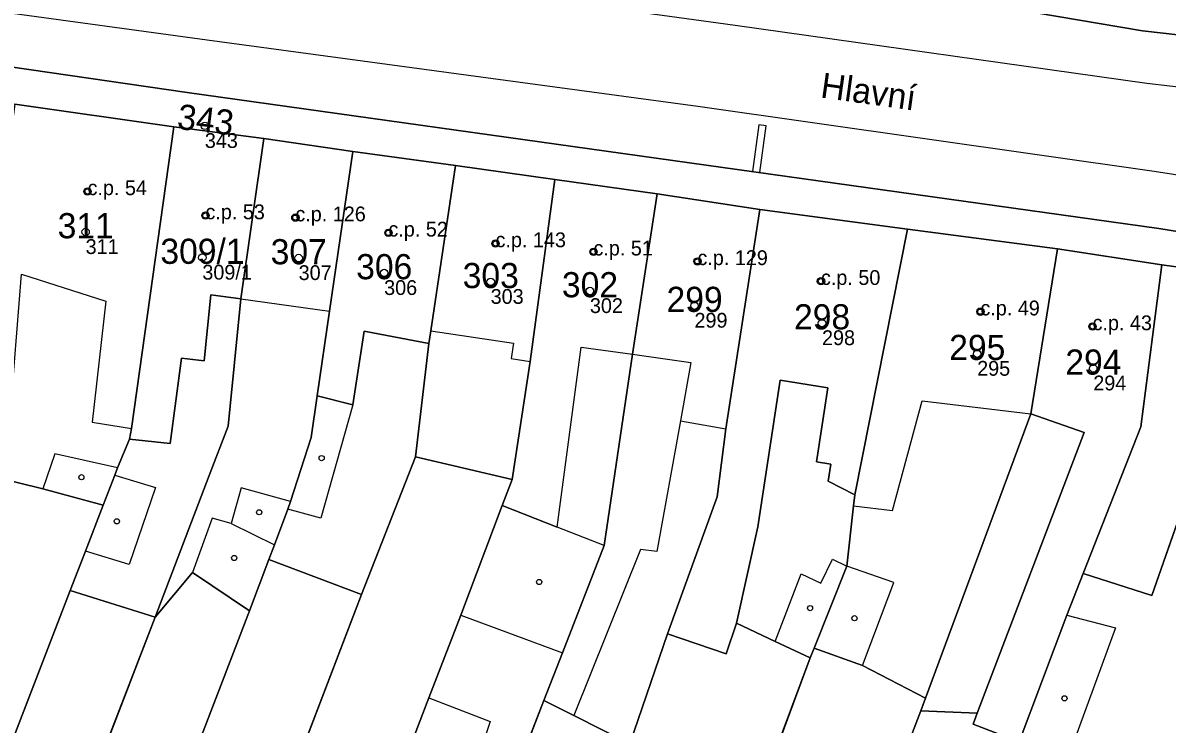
# Model space of a CAD drawing. Extents: x -603967 to -594699, y -1179315 to -1165625.
# Drawn here: x -597781.7 to -597704.3, y -1172370 to -1172322.6 of the extents above; entities that cross this region are included whole.
import ezdxf

# ---------------------------------------------------------------- set-up
doc = ezdxf.new("R2010")
doc.units = 0
for name, color, linetype in [('Definiční body', 7, 'Continuous'), ('Hranice parcel', 7, 'Continuous'), ('Parcelní čísla', 7, 'Continuous'), ('Polygon budovy', 7, 'Continuous'), ('Polygon parcely', 7, 'Continuous'), ('Pop  PČ popisy', 7, 'Continuous'), ('Vnitřní kresba', 7, 'Continuous'), ('Věcná břemena k části', 7, 'Continuous'), ('Značky budov', 7, 'Continuous')]:
    doc.layers.add(name, color=color, linetype=linetype)

msp = doc.modelspace()

# ---------------------------------------------------------------- linework, layer by layer
at = {"layer": 'Definiční body'}
for centre in [(-597769.38, -1172329.59994), (-597777.31, -1172334.02994), (-597769.34, -1172335.65994), (-597763.26, -1172335.79994), (-597777.44, -1172336.76994), (-597756.97, -1172336.82994), (-597749.73, -1172337.54994), (-597743.11, -1172338.10994), (-597769.55, -1172338.49994), (-597763.04, -1172338.52994), (-597736.08, -1172338.75994), (-597757.26, -1172339.53994), (-597750.06, -1172340.13994), (-597727.73, -1172340.09994), (-597743.35, -1172340.75994), (-597736.28, -1172341.74994), (-597716.95, -1172342.15994), (-597727.66, -1172342.92994), (-597709.37, -1172343.15994), (-597717.17, -1172344.99994), (-597709.32, -1172345.98994)]:
    msp.add_circle(centre, 0.25, dxfattribs=at)
at = {"layer": 'Hranice parcel'}
for p, q in [((-597771.48, -1172329.67), (-597782.22, -1172328.12)), ((-597765.4, -1172330.46), (-597771.48, -1172329.67)), ((-597765.4, -1172330.46), (-597766.94, -1172341.3)), ((-597759.38, -1172331.34), (-597765.4, -1172330.46)), ((-597760.96, -1172342.12), (-597759.38, -1172331.34)), ((-597759.38, -1172331.34), (-597752.44, -1172332.27)), ((-597745.71, -1172333.23), (-597752.44, -1172332.27)), ((-597738.8, -1172334.2), (-597745.71, -1172333.23)), ((-597731.86, -1172335.26), (-597738.8, -1172334.2)), ((-597721.89, -1172336.59), (-597731.86, -1172335.26)), ((-597721.89, -1172336.59), (-597725.43, -1172354.54)), ((-597711.75, -1172337.91), (-597721.89, -1172336.59)), ((-597704.68, -1172338.99), (-597711.75, -1172337.91)), ((-597691.02, -1172340.89), (-597704.68, -1172338.99)), ((-597754.24, -1172344.3), (-597755.15, -1172351.97)), ((-597763.58, -1172355), (-597762.19, -1172350.67)), ((-597755.15, -1172351.97), (-597758.79, -1172361.28)), ((-597755.15, -1172351.97), (-597748.61, -1172353.5)), ((-597769.08, -1172353.23), (-597772.73, -1172362.82)), ((-597766.37, -1172362.38), (-597765.05, -1172358.92)), ((-597758.79, -1172361.28), (-597765.05, -1172358.92)), ((-597710, -1172359.85), (-597711.11, -1172362.67)), ((-597778.48, -1172361.01), (-597796.02, -1172406.49)), ((-597758.79, -1172361.28), (-597789.15, -1172440.56)), ((-597778.48, -1172361.01), (-597772.73, -1172362.82)), ((-597772.73, -1172362.82), (-597801.55, -1172437.37)), ((-597793.43, -1172432.8), (-597766.37, -1172362.38)), ((-597711.11, -1172362.67), (-597714.34, -1172371.24)), ((-597733.43, -1172363.22), (-597730.82, -1172364.45)), ((-597740.64, -1172371.37), (-597738.11, -1172363.93)), ((-597730.82, -1172364.45), (-597728.45, -1172365.57)), ((-597728.2, -1172364.9), (-597728.45, -1172365.57)), ((-597728.2, -1172364.9), (-597724.93, -1172366.07)), ((-597728.45, -1172365.57), (-597747.04, -1172415.37)), ((-597724.93, -1172366.07), (-597720.66, -1172368.28)), ((-597746.46, -1172368.45), (-597748.35, -1172373.32)), ((-597720.66, -1172368.28), (-597720.99, -1172369.15)), ((-597720.99, -1172369.15), (-597752, -1172449.92))]:
    msp.add_line(p, q, dxfattribs=at)
for points in [[(-597661.75, -1172328.26), (-597662.94, -1172328.05), (-597706, -1172323.18), (-597731.68, -1172318.8)], [(-597737.75, -1172331.93), (-597770.58, -1172327.35), (-597797.27, -1172323.47)], [(-597771.48, -1172329.67), (-597774.33, -1172350.05), (-597774.47, -1172350.77), (-597775.28, -1172352.71)], [(-597752.44, -1172332.27), (-597754.11, -1172343.45), (-597754.24, -1172344.3)], [(-597674.14, -1172341.49), (-597704.89, -1172336.54), (-597737.75, -1172331.93)], [(-597745.71, -1172333.23), (-597747.39, -1172345.52), (-597748.61, -1172353.5)], [(-597738.8, -1172334.2), (-597740.48, -1172345.04), (-597742.38, -1172357.97), (-597745.2, -1172365.21), (-597746.46, -1172368.45)], [(-597731.86, -1172335.26), (-597734.16, -1172350.08), (-597734.74, -1172354.68), (-597738.11, -1172363.93)], [(-597711.75, -1172337.91), (-597713.55, -1172349.07), (-597720.66, -1172368.28)], [(-597704.68, -1172338.99), (-597706.11, -1172349.95), (-597710, -1172359.85)], [(-597766.94, -1172341.3), (-597767.81, -1172349.9), (-597769.08, -1172353.23)], [(-597762.19, -1172350.67), (-597761.78, -1172347.85), (-597760.96, -1172342.12)], [(-597776.25, -1172355.24), (-597780.33, -1172354.14), (-597787.02, -1172352.5)], [(-597775.28, -1172352.71), (-597775.47, -1172353.21), (-597776.25, -1172355.24)], [(-597748.61, -1172353.5), (-597749.28, -1172355.27), (-597752.08, -1172362.67), (-597754.24, -1172368.26), (-597755.24, -1172370.86)], [(-597765.05, -1172358.92), (-597764.67, -1172357.92), (-597763.77, -1172355.5), (-597763.58, -1172355)], [(-597725.43, -1172354.54), (-597725.53, -1172355.28), (-597725.99, -1172359.36), (-597728.2, -1172364.9)], [(-597776.25, -1172355.24), (-597777.45, -1172358.34), (-597778.48, -1172361.01)], [(-597772.73, -1172362.82), (-597770.22, -1172359.79), (-597766.37, -1172362.38)], [(-597738.11, -1172363.93), (-597734.13, -1172365.28), (-597733.43, -1172363.22)], [(-597746.46, -1172368.45), (-597744.44, -1172369.46), (-597740.64, -1172371.37)], [(-597714.34, -1172371.24), (-597717.44, -1172370.05), (-597717.16, -1172369.3), (-597720.99, -1172369.15)]]:
    msp.add_lwpolyline(points, dxfattribs=at)
at = {"layer": 'Polygon budovy'}
for points in [[(-597771.48, -1172329.67), (-597782.22, -1172328.12), (-597784.8, -1172347.36), (-597782.4, -1172347.55), (-597781.78, -1172339.62), (-597776.08, -1172341.44), (-597776.99, -1172349.62), (-597774.33, -1172350.05)], [(-597774.47, -1172350.77), (-597771.73, -1172351.06), (-597770.97, -1172345.31), (-597769.43, -1172345.48), (-597768.97, -1172341.02), (-597766.94, -1172341.3), (-597765.4, -1172330.46), (-597771.48, -1172329.67), (-597774.33, -1172350.05)], [(-597765.4, -1172330.46), (-597766.94, -1172341.3), (-597760.96, -1172342.12), (-597759.38, -1172331.34)], [(-597761.78, -1172347.85), (-597759.37, -1172348.45), (-597758.62, -1172343.47), (-597754.24, -1172344.3), (-597754.11, -1172343.45), (-597752.44, -1172332.27), (-597759.38, -1172331.34), (-597760.96, -1172342.12)], [(-597752.44, -1172332.27), (-597754.11, -1172343.45), (-597748.52, -1172344.29), (-597748.68, -1172345.32), (-597747.39, -1172345.52), (-597745.71, -1172333.23)], [(-597748.61, -1172353.5), (-597749.28, -1172355.27), (-597745.56, -1172356.72), (-597743.93, -1172344.56), (-597740.48, -1172345.04), (-597738.8, -1172334.2), (-597745.71, -1172333.23), (-597747.39, -1172345.52)], [(-597737.23, -1172349.53), (-597734.16, -1172350.08), (-597731.86, -1172335.26), (-597738.8, -1172334.2), (-597740.48, -1172345.04), (-597736.52, -1172345.59)], [(-597738.11, -1172363.93), (-597734.13, -1172365.28), (-597733.43, -1172363.22), (-597731.99, -1172356.71), (-597730.48, -1172346.79), (-597727.26, -1172347.3), (-597728.04, -1172352.3), (-597727.06, -1172352.46), (-597727.24, -1172353.62), (-597725.43, -1172354.54), (-597721.89, -1172336.59), (-597731.86, -1172335.26), (-597734.16, -1172350.08), (-597734.74, -1172354.68)], [(-597725.43, -1172354.54), (-597725.53, -1172355.28), (-597722.9, -1172355.59), (-597720.88, -1172348.19), (-597713.55, -1172349.07), (-597711.75, -1172337.91), (-597721.89, -1172336.59)], [(-597717.44, -1172370.05), (-597714.34, -1172371.24), (-597711.11, -1172362.67), (-597710, -1172359.85), (-597706.11, -1172349.95), (-597704.68, -1172338.99), (-597711.75, -1172337.91), (-597713.55, -1172349.07), (-597709.94, -1172350.33), (-597717.16, -1172369.3)], [(-597706.11, -1172349.95), (-597710, -1172359.85), (-597705.37, -1172361.34), (-597701.54, -1172350.39), (-597699.58, -1172350.78), (-597692.76, -1172351.8), (-597691.02, -1172340.89), (-597704.68, -1172338.99)]]:
    msp.add_lwpolyline(points, close=True, dxfattribs=at)
at = {"layer": 'Polygon parcely'}
for points in [[(-597534.75, -1172348.6), (-597559.28, -1172345.76), (-597603.32, -1172338.5), (-597661.75, -1172328.26), (-597662.94, -1172328.05), (-597706, -1172323.18), (-597731.68, -1172318.8), (-597765.64, -1172314.46), (-597793.13, -1172310.44), (-597851.99, -1172302.61), (-597960.77, -1172287.58), (-597964.7, -1172286.91), (-597986.41, -1172283.87), (-598031.69, -1172277.53)], [(-598037.57, -1172289.67), (-597969.21, -1172299.41), (-597966.22, -1172299.84), (-597956.98, -1172301.12), (-597797.27, -1172323.47), (-597770.58, -1172327.35), (-597737.75, -1172331.93), (-597704.89, -1172336.54), (-597674.14, -1172341.49), (-597673.16, -1172341.62), (-597665.62, -1172342.61), (-597661.18, -1172343.19), (-597660.8, -1172342.11), (-597591.42, -1172351.56), (-597523.81, -1172359.42)], [(-597674.14, -1172341.49), (-597704.89, -1172336.54), (-597737.75, -1172331.93), (-597770.58, -1172327.35), (-597797.27, -1172323.47), (-597956.98, -1172301.12)], [(-597851.99, -1172302.61), (-597793.13, -1172310.44), (-597765.64, -1172314.46), (-597731.68, -1172318.8), (-597706, -1172323.18), (-597662.94, -1172328.05)], [(-597837.68, -1172320.18), (-597823.64, -1172322), (-597812.09, -1172323.71), (-597798.01, -1172325.85), (-597791.02, -1172326.88), (-597782.22, -1172328.12), (-597771.48, -1172329.67), (-597765.4, -1172330.46), (-597759.38, -1172331.34), (-597752.44, -1172332.27), (-597745.71, -1172333.23), (-597738.8, -1172334.2), (-597731.86, -1172335.26), (-597721.89, -1172336.59), (-597711.75, -1172337.91), (-597704.68, -1172338.99), (-597691.02, -1172340.89)]]:
    msp.add_lwpolyline(points, dxfattribs=at)
for points in [[(-597782.22, -1172328.12), (-597784.8, -1172347.36), (-597785.63, -1172349.15), (-597787.02, -1172352.5), (-597780.33, -1172354.14), (-597776.25, -1172355.24), (-597775.47, -1172353.21), (-597775.28, -1172352.71), (-597774.47, -1172350.77), (-597774.33, -1172350.05), (-597771.48, -1172329.67)], [(-597771.48, -1172329.67), (-597774.33, -1172350.05), (-597774.47, -1172350.77), (-597775.28, -1172352.71), (-597775.47, -1172353.21), (-597776.25, -1172355.24), (-597777.45, -1172358.34), (-597778.48, -1172361.01), (-597772.73, -1172362.82), (-597769.08, -1172353.23), (-597767.81, -1172349.9), (-597766.94, -1172341.3), (-597765.4, -1172330.46)], [(-597766.37, -1172362.38), (-597765.05, -1172358.92), (-597764.67, -1172357.92), (-597763.77, -1172355.5), (-597763.58, -1172355), (-597762.19, -1172350.67), (-597761.78, -1172347.85), (-597760.96, -1172342.12), (-597759.38, -1172331.34), (-597765.4, -1172330.46), (-597766.94, -1172341.3), (-597767.81, -1172349.9), (-597769.08, -1172353.23), (-597772.73, -1172362.82), (-597770.22, -1172359.79)], [(-597755.15, -1172351.97), (-597754.24, -1172344.3), (-597754.11, -1172343.45), (-597752.44, -1172332.27), (-597759.38, -1172331.34), (-597760.96, -1172342.12), (-597761.78, -1172347.85), (-597762.19, -1172350.67), (-597763.58, -1172355), (-597763.77, -1172355.5), (-597764.67, -1172357.92), (-597765.05, -1172358.92), (-597758.79, -1172361.28)], [(-597752.44, -1172332.27), (-597754.11, -1172343.45), (-597754.24, -1172344.3), (-597755.15, -1172351.97), (-597748.61, -1172353.5), (-597747.39, -1172345.52), (-597745.71, -1172333.23)], [(-597750.91, -1172372.35), (-597748.35, -1172373.32), (-597746.46, -1172368.45), (-597745.2, -1172365.21), (-597742.38, -1172357.97), (-597740.48, -1172345.04), (-597738.8, -1172334.2), (-597745.71, -1172333.23), (-597747.39, -1172345.52), (-597748.61, -1172353.5), (-597749.28, -1172355.27), (-597752.08, -1172362.67), (-597754.24, -1172368.26), (-597755.24, -1172370.86)], [(-597740.64, -1172371.37), (-597738.11, -1172363.93), (-597734.74, -1172354.68), (-597734.16, -1172350.08), (-597731.86, -1172335.26), (-597738.8, -1172334.2), (-597740.48, -1172345.04), (-597742.38, -1172357.97), (-597745.2, -1172365.21), (-597746.46, -1172368.45), (-597744.44, -1172369.46)], [(-597733.43, -1172363.22), (-597730.82, -1172364.45), (-597728.45, -1172365.57), (-597728.2, -1172364.9), (-597725.99, -1172359.36), (-597725.53, -1172355.28), (-597725.43, -1172354.54), (-597721.89, -1172336.59), (-597731.86, -1172335.26), (-597734.16, -1172350.08), (-597734.74, -1172354.68), (-597738.11, -1172363.93), (-597734.13, -1172365.28)], [(-597721.89, -1172336.59), (-597725.43, -1172354.54), (-597725.53, -1172355.28), (-597725.99, -1172359.36), (-597728.2, -1172364.9), (-597724.93, -1172366.07), (-597720.66, -1172368.28), (-597713.55, -1172349.07), (-597711.75, -1172337.91)], [(-597720.66, -1172368.28), (-597720.99, -1172369.15), (-597717.16, -1172369.3), (-597717.44, -1172370.05), (-597714.34, -1172371.24), (-597711.11, -1172362.67), (-597710, -1172359.85), (-597706.11, -1172349.95), (-597704.68, -1172338.99), (-597711.75, -1172337.91), (-597713.55, -1172349.07)], [(-597711.13, -1172372.59), (-597701.59, -1172374.92), (-597698.18, -1172366.22), (-597696.41, -1172361.13), (-597692.76, -1172351.8), (-597691.02, -1172340.89), (-597704.68, -1172338.99), (-597706.11, -1172349.95), (-597710, -1172359.85), (-597711.11, -1172362.67), (-597714.34, -1172371.24), (-597714.53, -1172371.77)], [(-597758.79, -1172361.28), (-597789.15, -1172440.56), (-597782.45, -1172442.31), (-597782.32, -1172441.9), (-597780.22, -1172436.14), (-597755.24, -1172370.86), (-597754.24, -1172368.26), (-597752.08, -1172362.67), (-597749.28, -1172355.27), (-597748.61, -1172353.5), (-597755.15, -1172351.97)], [(-597801.67, -1172404.22), (-597796.02, -1172406.49), (-597778.48, -1172361.01), (-597777.45, -1172358.34), (-597776.25, -1172355.24), (-597780.33, -1172354.14), (-597787.02, -1172352.5), (-597788.42, -1172355.44), (-597803.75, -1172395.8), (-597799.04, -1172397.63)], [(-597793.43, -1172432.8), (-597790.31, -1172433.99), (-597792.53, -1172439.78), (-597789.15, -1172440.56), (-597758.79, -1172361.28), (-597765.05, -1172358.92), (-597766.37, -1172362.38)], [(-597795.64, -1172438.59), (-597793.43, -1172432.8), (-597766.37, -1172362.38), (-597770.22, -1172359.79), (-597772.73, -1172362.82), (-597801.55, -1172437.37), (-597795.78, -1172438.96)], [(-597796.02, -1172406.49), (-597807.31, -1172435.77), (-597801.55, -1172437.37), (-597772.73, -1172362.82), (-597778.48, -1172361.01)], [(-597756.46, -1172412.58), (-597747.04, -1172415.37), (-597728.45, -1172365.57), (-597730.82, -1172364.45), (-597733.43, -1172363.22), (-597734.13, -1172365.28), (-597738.11, -1172363.93), (-597740.64, -1172371.37)], [(-597759.28, -1172448.14), (-597752, -1172449.92), (-597720.99, -1172369.15), (-597720.66, -1172368.28), (-597724.93, -1172366.07), (-597728.2, -1172364.9), (-597728.45, -1172365.57), (-597747.04, -1172415.37)], [(-597756.46, -1172412.58), (-597740.64, -1172371.37), (-597744.44, -1172369.46), (-597746.46, -1172368.45), (-597748.35, -1172373.32), (-597775.81, -1172444), (-597769.17, -1172445.68)], [(-597744.72, -1172451.7), (-597729.3, -1172410.88), (-597723.41, -1172395.27), (-597714.53, -1172371.77), (-597714.34, -1172371.24), (-597717.44, -1172370.05), (-597717.16, -1172369.3), (-597720.99, -1172369.15), (-597752, -1172449.92)]]:
    msp.add_lwpolyline(points, close=True, dxfattribs=at)
at = {"layer": 'Vnitřní kresba'}
for p, q in [((-597733.54, -1172322.81), (-597767.07, -1172318.19)), ((-597769.23, -1172323.8), (-597796.21, -1172320.14)), ((-597705.71, -1172326.74), (-597733.54, -1172322.81)), ((-597736.06, -1172328.28), (-597769.23, -1172323.8)), ((-597665.47, -1172331.4), (-597705.71, -1172326.74)), ((-597705.21, -1172332.68), (-597736.06, -1172328.28)), ((-597670.59, -1172337.95), (-597705.21, -1172332.68)), ((-597781.78, -1172339.62), (-597776.08, -1172341.44)), ((-597768.97, -1172341.02), (-597769.43, -1172345.48)), ((-597766.94, -1172341.3), (-597768.97, -1172341.02)), ((-597776.08, -1172341.44), (-597776.99, -1172349.62)), ((-597766.94, -1172341.3), (-597760.96, -1172342.12)), ((-597758.62, -1172343.47), (-597759.37, -1172348.45)), ((-597754.24, -1172344.3), (-597758.62, -1172343.47)), ((-597754.11, -1172343.45), (-597748.52, -1172344.29)), ((-597748.52, -1172344.29), (-597748.68, -1172345.32)), ((-597745.56, -1172356.72), (-597743.93, -1172344.56)), ((-597743.93, -1172344.56), (-597740.48, -1172345.04)), ((-597740.48, -1172345.04), (-597736.52, -1172345.59)), ((-597770.97, -1172345.31), (-597771.73, -1172351.06)), ((-597769.43, -1172345.48), (-597770.97, -1172345.31)), ((-597748.68, -1172345.32), (-597747.39, -1172345.52)), ((-597736.52, -1172345.59), (-597737.23, -1172349.53)), ((-597730.48, -1172346.79), (-597731.99, -1172356.71)), ((-597727.26, -1172347.3), (-597730.48, -1172346.79)), ((-597728.04, -1172352.3), (-597727.26, -1172347.3)), ((-597759.37, -1172348.45), (-597761.78, -1172347.85)), ((-597759.37, -1172348.45), (-597761.55, -1172356.12)), ((-597722.9, -1172355.59), (-597720.88, -1172348.19)), ((-597720.88, -1172348.19), (-597713.55, -1172349.07)), ((-597776.99, -1172349.62), (-597774.33, -1172350.05)), ((-597737.23, -1172349.53), (-597738.83, -1172358.38)), ((-597737.23, -1172349.53), (-597734.16, -1172350.08)), ((-597709.94, -1172350.33), (-597713.55, -1172349.07)), ((-597717.16, -1172369.3), (-597709.94, -1172350.33)), ((-597701.54, -1172350.39), (-597705.37, -1172361.34)), ((-597771.73, -1172351.06), (-597774.47, -1172350.77)), ((-597779.53, -1172351.76), (-597780.33, -1172354.14)), ((-597775.28, -1172352.71), (-597779.53, -1172351.76)), ((-597727.06, -1172352.46), (-597728.04, -1172352.3)), ((-597727.24, -1172353.62), (-597727.06, -1172352.46)), ((-597775.47, -1172353.21), (-597772.71, -1172354.05)), ((-597772.71, -1172354.05), (-597774.49, -1172359.26)), ((-597766.92, -1172354.06), (-597767.6, -1172356.47)), ((-597763.58, -1172355), (-597766.92, -1172354.06)), ((-597725.43, -1172354.54), (-597727.24, -1172353.62)), ((-597761.55, -1172356.12), (-597763.77, -1172355.5)), ((-597745.56, -1172356.72), (-597749.28, -1172355.27)), ((-597725.53, -1172355.28), (-597722.9, -1172355.59)), ((-597768.89, -1172356.11), (-597770.22, -1172359.79)), ((-597767.6, -1172356.47), (-597768.89, -1172356.11)), ((-597767.6, -1172356.47), (-597764.67, -1172357.92)), ((-597742.38, -1172357.97), (-597745.56, -1172356.72)), ((-597731.99, -1172356.71), (-597733.43, -1172363.22)), ((-597774.49, -1172359.26), (-597777.45, -1172358.34)), ((-597739.92, -1172358.23), (-597744.44, -1172369.46)), ((-597738.83, -1172358.38), (-597739.92, -1172358.23)), ((-597727.74, -1172360.51), (-597726.96, -1172358.9)), ((-597726.96, -1172358.9), (-597725.99, -1172359.36)), ((-597722.81, -1172360.46), (-597725.99, -1172359.36)), ((-597730.82, -1172364.45), (-597729.06, -1172359.88)), ((-597729.06, -1172359.88), (-597727.74, -1172360.51)), ((-597724.93, -1172366.07), (-597722.81, -1172360.46)), ((-597705.37, -1172361.34), (-597710, -1172359.85)), ((-597752.08, -1172362.67), (-597745.2, -1172365.21)), ((-597711.11, -1172362.67), (-597707.83, -1172363.53)), ((-597707.83, -1172363.53), (-597711.13, -1172372.59)), ((-597754.24, -1172368.26), (-597750.09, -1172369.87)), ((-597750.09, -1172369.87), (-597750.91, -1172372.35))]:
    msp.add_line(p, q, dxfattribs=at)
at = {"layer": 'Věcná břemena k části'}
msp.add_lwpolyline([(-597732.36, -1172332.69), (-597731.86, -1172332.76), (-597731.43, -1172329.6), (-597731.93, -1172329.53)], close=True, dxfattribs=at)
at = {"layer": 'Značky budov'}
for centre in [(-597777.3168, -1172334.02916), (-597769.3468, -1172335.65916), (-597763.2668, -1172335.79916), (-597756.9768, -1172336.82916), (-597749.7368, -1172337.54916), (-597743.1168, -1172338.10916), (-597736.0868, -1172338.75916), (-597727.7368, -1172340.09916), (-597716.9568, -1172342.15916), (-597709.3768, -1172343.15916), (-597761.4868, -1172352.05916), (-597777.7268, -1172353.34916), (-597765.7068, -1172355.71916), (-597775.3268, -1172356.32916), (-597767.3968, -1172358.80916), (-597746.7768, -1172360.42916), (-597728.4668, -1172362.19916), (-597725.4668, -1172362.87916), (-597711.2668, -1172368.29916)]:
    msp.add_circle(centre, 0.175, dxfattribs=at)

# ---------------------------------------------------------------- texts
at = {"layer": 'Definiční body'}
for s, p in [('343', (-597769.38, -1172331.089)), ('c.p. 54', (-597777.31, -1172334.28)), ('c.p. 53', (-597769.34, -1172335.91)), ('c.p. 126', (-597763.26, -1172336.05)), ('c.p. 52', (-597756.97, -1172337.08)), ('311', (-597777.44, -1172338.259)), ('c.p. 143', (-597749.73, -1172337.8)), ('c.p. 51', (-597743.11, -1172338.36)), ('c.p. 129', (-597736.08, -1172339.01)), ('309/1', (-597769.55, -1172339.989)), ('307', (-597763.04, -1172340.019)), ('c.p. 50', (-597727.73, -1172340.35)), ('306', (-597757.26, -1172341.029)), ('303', (-597750.06, -1172341.629)), ('302', (-597743.35, -1172342.249)), ('c.p. 49', (-597716.95, -1172342.41)), ('299', (-597736.28, -1172343.239)), ('c.p. 43', (-597709.37, -1172343.41)), ('298', (-597727.66, -1172344.419)), ('295', (-597717.17, -1172346.489)), ('294', (-597709.32, -1172347.479))]:
    msp.add_text(s, height=0.999996, dxfattribs=at).set_placement(p)
at = {"layer": 'Parcelní čísla'}
msp.add_text('343', height=1.699998, rotation=353, dxfattribs=at).set_placement((-597771.308, -1172329.791))
for s, p in [('311', (-597779.33, -1172337.195)), ('309/1', (-597772.386, -1172338.925)), ('307', (-597764.93, -1172338.955)), ('306', (-597759.15, -1172339.965)), ('303', (-597751.95, -1172340.565)), ('302', (-597745.24, -1172341.185)), ('299', (-597738.17, -1172342.175)), ('298', (-597729.55, -1172343.355)), ('295', (-597719.06, -1172345.425)), ('294', (-597711.21, -1172346.415))]:
    msp.add_text(s, height=1.699998, dxfattribs=at).set_placement(p)
at = {"layer": 'Pop  PČ popisy'}
msp.add_text('Hlavní', height=1.699998, rotation=351.9999972, dxfattribs=at).set_placement((-597727.82, -1172327.67))

doc.saveas('drawing.dxf')
